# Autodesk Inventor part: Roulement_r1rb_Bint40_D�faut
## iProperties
Created: 2011-01
Part Number: Roulement_r1rb_Bint40_D�faut
Document SubType Name: Modeling
Designer: eric
Density: 1 g/cm^3
Mass: 2.35584 g
Surface Area: 19.7997 cm^2
Volume: 2.35584 cm^3
Author: eric
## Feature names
1. Base1
